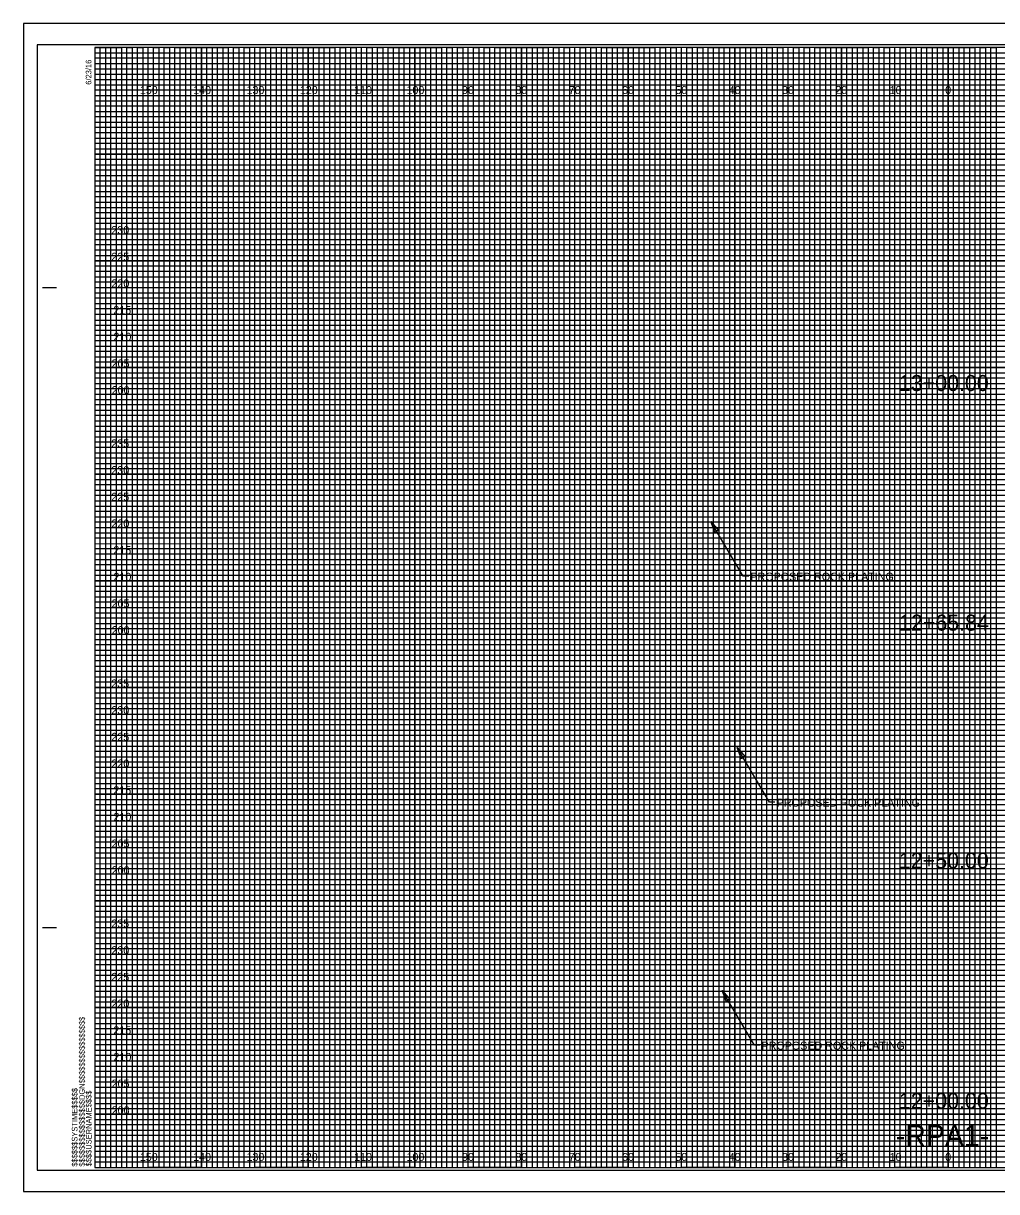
# Model space of a CAD drawing. Extents: x -13 to 323, y -5 to 654.
# Drawn here: x -13.4 to 169.1, y 215.5 to 434.5 of the extents above; entities that cross this region are included whole.
import ezdxf

# ---------------------------------------------------------------- set-up
doc = ezdxf.new("R2010")
doc.units = 0
for name, color, linetype in [('Prop CMT Concrete Structures', 7, 'Continuous'), ('Prop Terminator CELL', 7, 'Continuous'), ('Prop XS Alignment Label', 7, 'Continuous'), ('Prop XS Elevation Labels', 7, 'Continuous'), ('Prop XS Offset Labels', 7, 'Continuous'), ('Prop XS SE Text', 7, 'Continuous'), ('Prop XS Station Labels', 7, 'Continuous'), ('Sheet Cross Section CELL', 7, 'Continuous'), ('Sheet Cross Section Grid Major CELL', 7, 'Continuous'), ('Sheet Cross Section Grid Middle CELL', 7, 'Continuous'), ('Sheet Cross Section Grid Minor 1 CELL', 7, 'Continuous'), ('Sheet Cross Section Grid Minor 2 CELL', 7, 'Continuous'), ('Sheet Cutting Line CELL', 7, 'Continuous'), ('Sheet DOT Grid CELL', 7, 'Continuous'), ('Sheet Plot Border Inside CELL', 7, 'Continuous'), ('Sheet Plot Border Outside CELL', 7, 'Continuous')]:
    doc.layers.add(name, color=color, linetype=linetype)

msp = doc.modelspace()

# ---------------------------------------------------------------- linework, layer by layer
at = {"layer": 'Prop CMT Concrete Structures'}
for points in [[(122.62, 330.86), (121.59, 330.86), (115.52, 341.1)], [(127.53, 288.49), (126.51, 288.49), (120.43, 298.73)], [(124.7, 242.94), (123.68, 242.94), (117.6, 253.18)]]:
    msp.add_lwpolyline(points, dxfattribs=at)
at = {"layer": 'Prop Terminator CELL'}
for points in [[(116.33, 338.97), (115.52, 341.1), (117.01, 339.36), (116.52, 339.4)], [(121.25, 296.6), (120.43, 298.73), (121.93, 296.99), (121.44, 297.03)], [(118.42, 251.05), (117.6, 253.18), (119.1, 251.44), (118.61, 251.48)]]:
    msp.add_lwpolyline(points, close=True, dxfattribs=at)
at = {"layer": 'Sheet Cross Section CELL'}
for p, q in [((-9.8, 385), (-7.3, 385)), ((-9.7, 385), (-7.2, 385)), ((-9.8, 265), (-7.3, 265)), ((-9.7, 265), (-7.2, 265)), ((0, 220), (0, 220)), ((0, 220), (0, 220)), ((0, 220), (0, 220)), ((0, 220), (0, 220)), ((0, 220), (0, 220)), ((0, 220), (0, 220)), ((0, 220), (0, 220))]:
    msp.add_line(p, q, dxfattribs=at)
msp.add_lwpolyline([(320, 430), (0, 430), (0, 220), (320, 220)], close=True, dxfattribs=at)
at = {"layer": 'Sheet Cross Section Grid Major CELL'}
for p, q in [((10, 430), (0, 430)), ((10, 220), (10, 430)), ((30, 430), (20, 430)), ((20, 430), (20, 220)), ((30, 220), (30, 430)), ((50, 430), (40, 430)), ((40, 430), (40, 220)), ((50, 220), (50, 430)), ((70, 430), (60, 430)), ((60, 430), (60, 220)), ((70, 220), (70, 430)), ((90, 430), (80, 430)), ((80, 430), (80, 220)), ((90, 220), (90, 430)), ((110, 430), (100, 430)), ((100, 430), (100, 220)), ((110, 220), (110, 430)), ((130, 430), (120, 430)), ((120, 430), (120, 220)), ((130, 220), (130, 430)), ((150, 430), (140, 430)), ((140, 430), (140, 220)), ((150, 220), (150, 430)), ((170, 430), (160, 430)), ((160, 430), (160, 220)), ((20, 220), (10, 220)), ((40, 220), (30, 220)), ((60, 220), (50, 220)), ((80, 220), (70, 220)), ((100, 220), (90, 220)), ((120, 220), (110, 220)), ((140, 220), (130, 220)), ((160, 220), (150, 220))]:
    msp.add_line(p, q, dxfattribs=at)
for points in [[(0, 420), (320, 420), (320, 410), (0, 410)], [(0, 400), (320, 400), (320, 390), (0, 390)], [(0, 380), (320, 380), (320, 370), (0, 370)], [(0, 360), (320, 360), (320, 350), (0, 350)], [(0, 340), (320, 340), (320, 330), (0, 330)], [(0, 320), (320, 320), (320, 310), (0, 310)], [(0, 300), (320, 300), (320, 290), (0, 290)], [(0, 280), (320, 280), (320, 270), (0, 270)], [(0, 260), (320, 260), (320, 250), (0, 250)], [(0, 240), (320, 240), (320, 230), (0, 230)]]:
    msp.add_lwpolyline(points, dxfattribs=at)
at = {"layer": 'Sheet Cross Section Grid Middle CELL'}
for points in [[(0, 430), (5, 430), (5, 220), (15, 220), (15, 430), (25, 430), (25, 220), (35, 220), (35, 430), (45, 430), (45, 220), (55, 220), (55, 430), (65, 430), (65, 220), (75, 220), (75, 430), (85, 430), (85, 220), (95, 220), (95, 430), (105, 430), (105, 220), (115, 220), (115, 430), (125, 430), (125, 220), (135, 220), (135, 430), (145, 430), (145, 220), (155, 220), (155, 430), (165, 430), (165, 220), (175, 220)], [(0, 425), (275, 425)], [(0, 405), (320, 405), (320, 415), (0, 415)], [(0, 385), (320, 385), (320, 395), (0, 395)], [(0, 365), (320, 365), (320, 375), (0, 375)], [(0, 345), (320, 345), (320, 355), (0, 355)], [(0, 325), (320, 325), (320, 335), (0, 335)], [(0, 305), (320, 305), (320, 315), (0, 315)], [(0, 285), (320, 285), (320, 295), (0, 295)], [(0, 265), (320, 265), (320, 275), (0, 275)], [(0, 245), (320, 245), (320, 255), (0, 255)], [(0, 225), (320, 225), (320, 235), (0, 235)]]:
    msp.add_lwpolyline(points, dxfattribs=at)
at = {"layer": 'Sheet Cross Section Grid Minor 1 CELL'}
for p, q in [((0, 429), (260, 429)), ((260, 427.98), (0, 427.98)), ((0, 427.98), (0, 427)), ((0, 427), (260, 427)), ((260, 425.89), (0, 425.89)), ((0, 425.89), (0, 424)), ((0, 424), (320, 424))]:
    msp.add_line(p, q, dxfattribs=at)
for points in [[(0, 423), (270, 423), (320, 423), (320, 422), (0, 422)], [(0, 421), (320, 421), (320, 419), (0, 419)], [(0, 418), (320, 418), (320, 417), (0, 416.98)], [(0, 416), (320, 416), (320, 414), (0, 414)], [(0, 413), (320, 413), (320, 412), (0, 412)], [(0, 411), (320, 411), (320, 409), (0, 409)], [(0, 408), (320, 408), (320, 407), (0, 407)], [(0, 406), (320, 406), (320, 404), (0, 404)], [(0, 403), (320, 403), (320, 402), (0, 402)], [(0, 401), (320, 401), (320, 399), (0, 399)], [(0, 398), (320, 398), (320, 397), (0, 397)], [(0, 396), (320, 396), (320, 393.95), (320, 393), (320, 392), (0, 392)], [(0, 394), (320, 394), (320, 393), (0, 393)], [(0, 391), (320, 391), (320, 389), (0, 389.03)], [(0, 389.03), (320, 389), (320, 388), (0, 388)], [(0, 387), (320, 387), (320, 386), (0, 386)], [(0, 384), (320, 384), (320, 383), (0, 383)], [(0, 382), (320, 382), (320, 381), (0, 381)], [(-0.07, 378.89), (320, 378.89), (320, 377.88), (-0.07, 377.88)], [(0, 377), (320, 377), (320, 376), (0, 376)], [(0, 374), (320, 374), (320, 373), (0, 373)], [(0, 372), (320, 372), (320, 371), (0, 371)], [(0, 369), (320, 369), (320, 368), (0, 368)], [(0, 367), (320, 367), (320, 366), (0, 366)], [(0, 364), (320, 364), (320, 363), (0, 363)], [(0, 362), (320, 362), (320, 361), (0, 361)], [(0, 359), (320, 359), (319.99, 357.98), (0, 358)], [(0, 357), (320, 357), (320, 356), (0, 356)], [(0, 354), (320, 354), (320, 353), (0, 353)], [(0, 352), (320, 352), (320, 351), (0, 351)], [(0, 349), (320, 349), (320, 348), (0, 348)], [(0, 347), (320, 347), (320, 346), (0, 346)], [(0, 344), (320, 344), (320, 343), (0, 343)], [(0, 342), (320, 342), (320, 341), (0, 341)], [(0, 339), (320, 339), (320, 338), (0, 338)], [(0, 336.99), (320.07, 336.91), (320, 336), (0, 336)], [(0, 334), (320, 334), (320, 333), (0, 333)], [(0, 332), (320, 332), (320, 331), (0, 331)], [(0, 329), (320, 329), (320, 328), (0, 328)], [(0, 327), (320, 327), (320, 326), (0, 326)], [(0, 324), (320, 324), (320, 323), (0, 323)], [(0, 322), (320, 322), (320, 321), (0, 321)], [(0, 319), (320, 319), (320, 318), (0, 318)], [(0, 317), (320, 317), (320, 316), (0, 316)], [(0, 314), (320, 314), (320, 313), (0, 313)], [(0, 312), (320, 312), (320, 311), (0, 311)], [(0, 309), (320, 309), (320, 308), (0, 308)], [(0, 307), (320, 307), (320, 306), (0, 306)], [(0, 304), (320, 304), (320, 303), (0, 303)], [(0, 302), (320, 302), (320, 301), (0, 301)], [(0, 299), (320, 299), (319.99, 297.98), (0, 298)], [(0, 297), (320, 297), (320, 296), (0, 296)], [(0, 294), (320, 294), (320, 293), (0, 293)], [(0, 292), (320, 292), (320, 291), (0, 291)], [(0, 289), (320, 289), (320, 288), (0, 288)], [(0, 287), (320, 287), (320, 286), (0, 286)], [(0, 284), (320, 284), (320, 283), (0, 283)], [(0, 282), (320, 282), (320, 281), (0, 281)], [(0, 279), (320, 279), (320, 278), (0, 278)], [(0, 276.99), (320.07, 276.91), (320, 276), (0, 276)], [(0, 274), (320, 274), (320, 273), (0, 273)], [(0, 272), (320, 272), (320, 271), (0, 271)], [(0, 269), (320, 269), (320, 268), (0, 268)], [(0, 267), (320, 267), (320, 266), (0, 266)], [(0, 264), (320, 264), (320, 263), (0, 263)], [(0, 262), (320, 262), (320, 261), (0, 261)], [(0, 259), (320, 259), (320, 258), (0, 258)], [(0, 257), (320, 257), (320, 256), (0, 256)], [(0, 254), (320, 254), (320, 253), (0, 253)], [(0, 252), (320, 252), (320, 251), (0, 251)], [(0, 249), (320, 249), (320, 248), (0, 248)], [(0, 247), (320, 247), (320, 246), (0, 246)], [(0, 244), (320, 244), (320, 243), (0, 243)], [(0, 242), (320, 242), (320, 241), (0, 241)], [(0, 239), (320, 239), (320, 238), (0, 238)], [(0, 237), (320, 237), (320, 236), (0, 236)], [(0, 234), (320, 234), (320, 233), (0, 233)], [(0, 232), (320, 232), (320, 231), (0, 231)], [(0, 229), (320, 229), (320, 228), (0, 228)], [(0, 227), (320, 227), (320, 226), (0, 226)], [(0, 224), (320, 224), (320, 223), (0, 223)], [(0, 222), (320, 222), (320, 221), (0, 221)]]:
    msp.add_lwpolyline(points, dxfattribs=at)
at = {"layer": 'Sheet Cross Section Grid Minor 2 CELL'}
for points in [[(0, 220), (1, 220), (1, 430), (2, 430), (2, 220)], [(2, 220), (3, 220), (3, 430), (4, 430), (4, 220)], [(5, 220), (6, 220), (6, 430), (7, 430), (7, 220)], [(7, 220), (8, 220), (8, 430), (9, 430), (9, 220)], [(10, 220), (11, 220), (11, 430), (12, 430), (12, 220)], [(12, 220), (13, 220), (13, 430), (14, 430), (14, 220)], [(15, 220), (16, 220), (16, 430), (17, 430), (17, 220)], [(17, 220), (18, 220), (18, 430), (19, 430), (19, 220)], [(20, 220), (21, 220), (21, 430), (22, 430), (22, 220)], [(22, 220), (23, 220), (23, 430), (24, 430), (24, 220)], [(25, 220), (26, 220), (26, 430), (27, 430), (27, 220)], [(27, 220), (28, 220), (28, 430), (29, 430), (29, 220)], [(30, 220), (31, 220), (31, 430), (32, 430), (32, 220)], [(32, 220), (33, 220), (33, 430), (34, 430), (34, 220)], [(35, 220), (36, 220), (36, 430), (37, 430), (37, 220)], [(37, 220), (38, 220), (38, 430), (39, 430), (39, 220)], [(40, 220), (41, 220), (41, 430), (42, 430), (42, 220)], [(42, 220), (43, 220), (43, 430), (44, 430), (44, 220)], [(45, 220), (46, 220), (46, 430), (47, 430), (47, 220)], [(47, 220), (48, 220), (48, 430), (49, 430), (49, 220)], [(50, 220), (51, 220), (51, 430), (52, 430), (52, 220)], [(52, 220), (53, 220), (53, 430), (54, 430), (54, 220)], [(55, 220), (56, 220), (56, 430), (57, 430), (57, 220)], [(57, 220), (58, 220), (58, 430), (59, 430), (59, 220)], [(60, 220), (61, 220), (61, 430), (62, 430), (62, 220)], [(62, 220), (63, 220), (63, 430), (64, 430), (64, 220)], [(65, 220), (66, 220), (66, 430), (67, 430), (67, 220)], [(67, 220), (68, 220), (68, 430), (69, 430), (69, 220)], [(70, 220), (71, 220), (71, 430), (72, 430), (72, 220)], [(72, 220), (73, 220), (73, 430), (74, 430), (74, 220)], [(75, 220), (76, 220), (76, 430), (77, 430), (77, 220)], [(77, 220), (78, 220), (78, 430), (79, 430), (79, 220)], [(80, 220), (81, 220), (81, 430), (82, 430), (82, 220)], [(82, 220), (83, 220), (83, 430), (84, 430), (84, 220)], [(85, 220), (86, 220), (86, 430), (87, 430), (87, 220)], [(87, 220), (88, 220), (88, 430), (89, 430), (89, 220)], [(90, 220), (91, 220), (91, 430), (92, 430), (92, 220)], [(92, 220), (93, 220), (93, 430), (94, 430), (94, 220)], [(95, 220), (96, 220), (96, 430), (97, 430), (97, 220)], [(97, 220), (98, 220), (98, 430), (99, 430), (99, 220)], [(100, 220), (101, 220), (101, 430), (102, 430), (102, 220)], [(102, 220), (103, 220), (103, 430), (104, 430), (104, 220)], [(105, 220), (106, 220), (106, 430), (107, 430), (107, 220)], [(107, 220), (108, 220), (108, 430), (109, 430), (109, 220)], [(110, 220), (111, 220), (111, 430), (112, 430), (112, 220)], [(112, 220), (113, 220), (113, 430), (114, 430), (114, 220)], [(115, 220), (116, 220), (116, 430), (117, 430), (117, 220)], [(117, 220), (118, 220), (118, 430), (119, 430), (119, 220)], [(120, 220), (121, 220), (121, 430), (122, 430), (122, 220)], [(122, 220), (123, 220), (123, 430), (124, 430), (124, 220)], [(125, 220), (126, 220), (126, 430), (127, 430), (127, 220)], [(127, 220), (128, 220), (128, 430), (129, 430), (129, 220)], [(130, 220), (131, 220), (131, 430), (132, 430), (132, 220)], [(132, 220), (133, 220), (133, 430), (134, 430), (134, 220)], [(135, 220), (136, 220), (136, 430), (137, 430), (137, 220)], [(137, 220), (138, 220), (138, 430), (139, 430), (139, 220)], [(140, 220), (141, 220), (141, 430), (142, 430), (142, 220)], [(142, 220), (143, 220), (143, 430), (144, 430), (144, 220)], [(145, 220), (146, 220), (146, 430), (147, 430), (147, 220)], [(147, 220), (148, 220), (148, 430), (149, 430), (149, 220)], [(150, 220), (151, 220), (151, 430), (152, 430), (152, 220)], [(152, 220), (153, 220), (153, 430), (154, 430), (154, 220)], [(155, 220), (156, 220), (156, 430), (157, 430), (157, 220)], [(157, 220), (158, 220), (158, 430), (159, 430), (159, 220)], [(160, 220), (161, 220), (161, 430), (162, 430), (162, 220)], [(162, 220), (163, 220), (163, 430), (164, 430), (164, 220)], [(165, 220), (166, 220), (166, 430), (167, 430), (167, 220)], [(167, 220), (168, 220), (168, 430), (169, 430), (169, 220)]]:
    msp.add_lwpolyline(points, dxfattribs=at)
at = {"layer": 'Sheet Cutting Line CELL'}
for p, q in [((323.3, 434.5), (-13.4, 434.5)), ((-13.4, 434.5), (-13.4, 215.5)), ((-13.4, 215.5), (323.3, 215.5))]:
    msp.add_line(p, q, dxfattribs=at)
at = {"layer": 'Sheet DOT Grid CELL'}
for p, q in [((10, 220), (10, 430)), ((20, 220), (20, 430)), ((30, 220), (30, 430)), ((40, 220), (40, 430)), ((50, 220), (50, 430)), ((60, 220), (60, 430)), ((70, 220), (70, 430)), ((80, 220), (80, 430)), ((90, 220), (90, 430)), ((100, 220), (100, 430)), ((110, 220), (110, 430)), ((120, 220), (120, 430)), ((130, 220), (130, 430)), ((140, 220), (140, 430)), ((150, 220), (150, 430)), ((160, 220), (160, 430)), ((0, 420), (320, 420)), ((0, 410), (320, 410)), ((0, 400), (320, 400)), ((0, 390), (320, 390)), ((0, 380), (320, 380)), ((0, 370), (320, 370)), ((0, 360), (320, 360)), ((0, 350), (320, 350)), ((0, 340), (320, 340)), ((0, 330), (320, 330)), ((0, 320), (320, 320)), ((0, 310), (320, 310)), ((0, 300), (320, 300)), ((0, 290), (320, 290)), ((0, 280), (320, 280)), ((0, 270), (320, 270)), ((0, 260), (320, 260)), ((0, 250), (320, 250)), ((0, 240), (320, 240)), ((0, 230), (320, 230))]:
    msp.add_line(p, q, dxfattribs=at)
at = {"layer": 'Sheet Plot Border Inside CELL'}
msp.add_lwpolyline([(-10.8, 219.5), (322.4, 219.5), (322.4, 430.5), (-10.8, 430.5)], close=True, dxfattribs=at)
at = {"layer": 'Sheet Plot Border Outside CELL'}
msp.add_lwpolyline([(-13.4, 215.5), (323.3, 215.5), (323.3, 434.5), (-13.4, 434.5)], close=True, dxfattribs=at)

# ---------------------------------------------------------------- texts
at = {"layer": 'Prop XS Alignment Label'}
msp.add_text('-RPA1-', height=4, dxfattribs=at).set_placement((150.18, 224))
at = {"layer": 'Prop XS Elevation Labels'}
for s, p in [('230', (3.11, 395)), ('225', (3.1, 390)), ('220', (3.12, 385)), ('215', (3.48, 380)), ('210', (3.5, 375)), ('205', (3.15, 370)), ('200', (3.17, 365)), ('235', (3.09, 355)), ('230', (3.11, 350)), ('225', (3.1, 345)), ('220', (3.12, 340)), ('215', (3.48, 335)), ('210', (3.5, 330)), ('205', (3.15, 325)), ('200', (3.17, 320)), ('235', (3.09, 310)), ('230', (3.11, 305)), ('225', (3.1, 300)), ('220', (3.12, 295)), ('215', (3.48, 290)), ('210', (3.5, 285)), ('205', (3.15, 280)), ('200', (3.17, 275)), ('235', (3.09, 265)), ('230', (3.11, 260)), ('225', (3.1, 255)), ('220', (3.12, 250)), ('215', (3.48, 245)), ('210', (3.5, 240)), ('205', (3.15, 235)), ('200', (3.17, 230))]:
    msp.add_text(s, height=1.5, dxfattribs=at).set_placement(p)
at = {"layer": 'Prop XS Offset Labels'}
for s, p in [('150', (8.44, 421.25)), ('140', (18.44, 421.25)), ('130', (28.44, 421.25)), ('120', (38.44, 421.25)), ('110', (48.62, 421.25)), ('100', (58.44, 421.25)), ('90', (68.86, 421.25)), ('80', (78.86, 421.25)), ('70', (88.86, 421.25)), ('60', (98.86, 421.25)), ('50', (108.86, 421.25)), ('40', (118.86, 421.25)), ('30', (128.86, 421.25)), ('20', (138.86, 421.25)), ('10', (149.04, 421.25)), ('0', (159.45, 421.25)), ('0', (159.45, 421.25)), ('150', (8.44, 221.25)), ('140', (18.44, 221.25)), ('130', (28.44, 221.25)), ('120', (38.44, 221.25)), ('110', (48.62, 221.25)), ('100', (58.44, 221.25)), ('90', (68.86, 221.25)), ('80', (78.86, 221.25)), ('70', (88.86, 221.25)), ('60', (98.86, 221.25)), ('50', (108.86, 221.25)), ('40', (118.86, 221.25)), ('30', (128.86, 221.25)), ('20', (138.86, 221.25)), ('10', (149.04, 221.25)), ('0', (159.45, 221.25)), ('0', (159.45, 221.25))]:
    msp.add_text(s, height=1.5, dxfattribs=at).set_placement(p)
at = {"layer": 'Prop XS SE Text'}
for p in [(122.94, 330.03), (127.85, 287.66), (125.02, 242.11)]:
    msp.add_text('PROPOSED ROCK PLATING', height=1.5, rotation=360, dxfattribs=at).set_placement(p)
at = {"layer": 'Prop XS Station Labels'}
for s, p in [('13+00.00', (150.77, 365.58)), ('12+65.84', (150.79, 320.66)), ('12+50.00', (150.77, 276.08)), ('12+00.00', (150.77, 231.03))]:
    msp.add_text(s, height=3, dxfattribs=at).set_placement(p)
at = {"layer": 'Sheet Cross Section CELL'}
for s, p in [('6/23/16', (-0.65, 423)), ('$$$$$$$$$$$$$$$$DGN$$$$$$$$$$$$$$$$', (-1.88, 220.18)), ('$$$$$$SYSTIME$$$$$', (-3.26, 220.18)), ('$$$$USERNAME$$$$', (-0.62, 220.23))]:
    msp.add_text(s, height=1.05, rotation=90, dxfattribs=at).set_placement(p)

doc.saveas('drawing.dxf')
